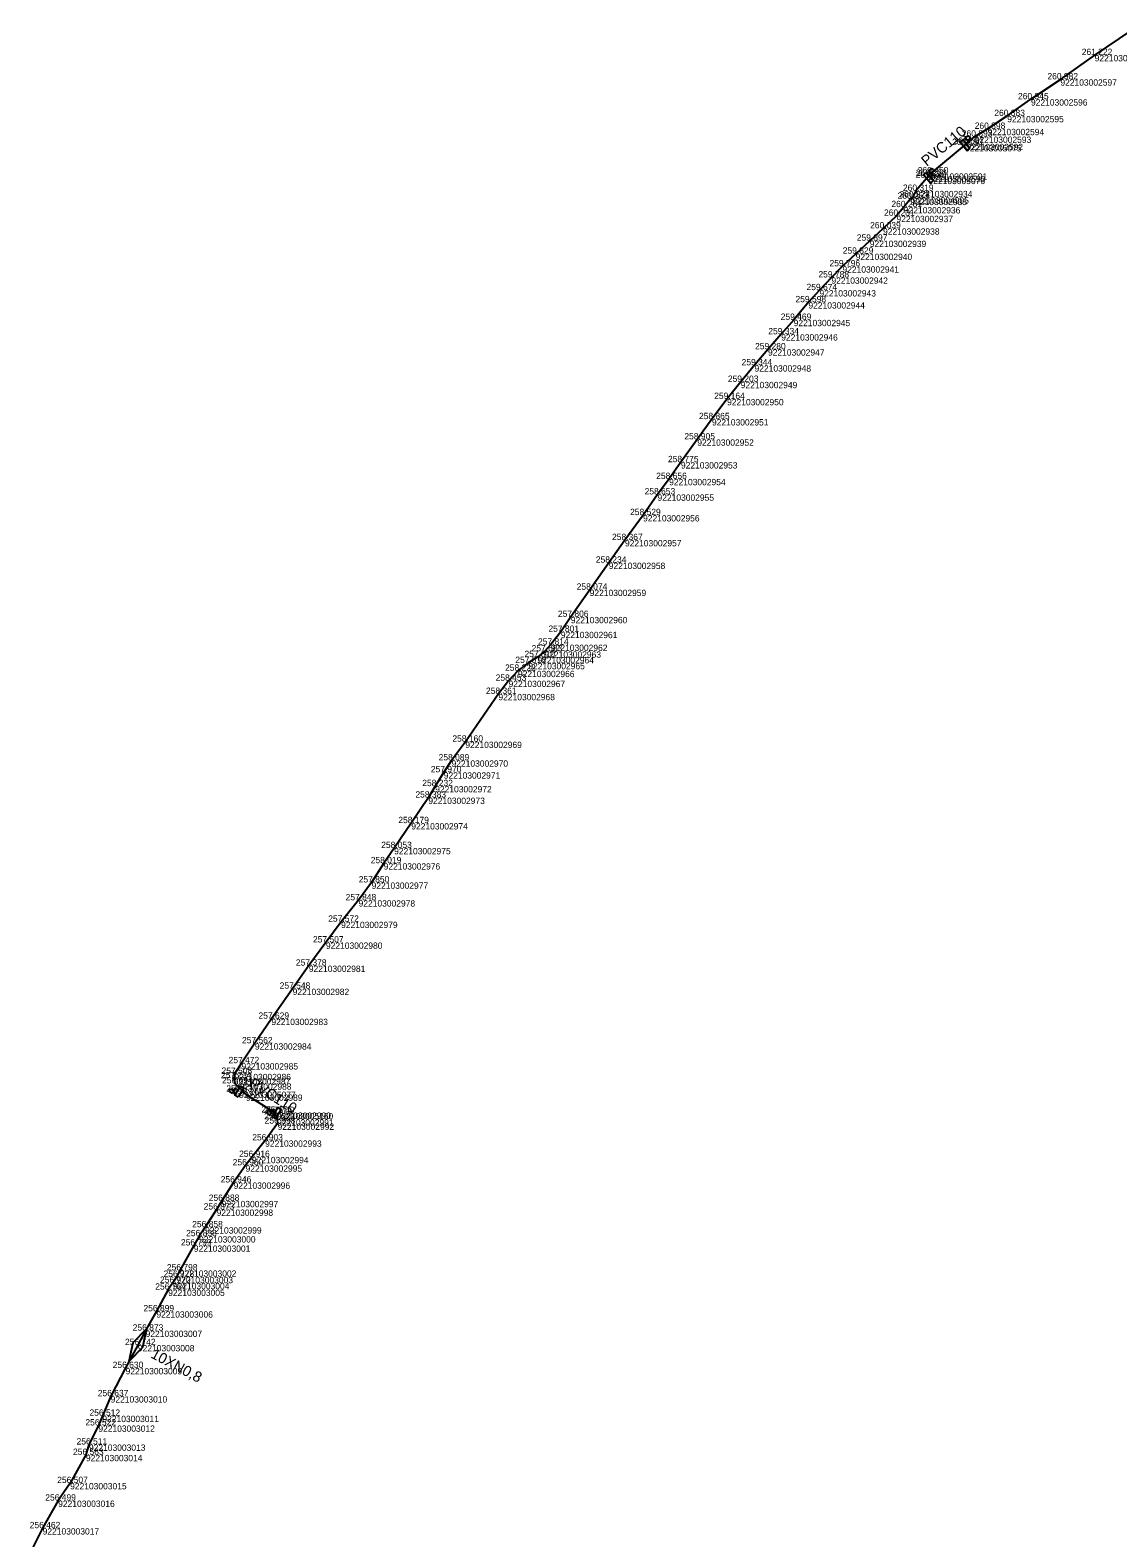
# Model space of a CAD drawing. Extents: x -771047 to -756200, y -1053876 to -1046520.
# Drawn here: x -762430.5 to -762224.4, y -1050712.5 to -1050426.6 of the extents above; entities that cross this region are included whole.
import ezdxf

# ---------------------------------------------------------------- set-up
doc = ezdxf.new("R2010")
doc.units = 0
for name, color, linetype in [('Vrstva 32', 7, 'Continuous'), ('Vrstva 33', 7, 'Continuous'), ('Vrstva 60', 7, 'Continuous'), ('Vrstva 61', 7, 'Continuous')]:
    doc.layers.add(name, color=color, linetype=linetype)

msp = doc.modelspace()

# ---------------------------------------------------------------- linework, layer by layer
at = {"layer": 'Vrstva 32'}
for points in [[(-762259.83, -1050453.72), (-762253.04, -1050448.11), (-762251.48, -1050446.73), (-762249.04, -1050445.27), (-762245.32, -1050442.83), (-762240.82, -1050439.66), (-762235.25, -1050435.88), (-762228.75, -1050431.27), (-762221.73, -1050426.55)], [(-762259.83, -1050453.72), (-762260.18, -1050454.18), (-762262.64, -1050457.03), (-762263.3, -1050458.27), (-762263.65, -1050458.53), (-762264.92, -1050460.11), (-762266.32, -1050461.76), (-762268.86, -1050464.14), (-762271.38, -1050466.48), (-762274.05, -1050468.94), (-762276.55, -1050471.34), (-762278.65, -1050473.45), (-762280.92, -1050475.86), (-762283.01, -1050478.15), (-762285.8, -1050481.49), (-762288.16, -1050484.22), (-762290.67, -1050487.07), (-762293.22, -1050490.1), (-762295.83, -1050493.25), (-762298.42, -1050496.49), (-762301.29, -1050500.32), (-762304.07, -1050504.16), (-762307.17, -1050508.48), (-762309.41, -1050511.66), (-762311.61, -1050514.6), (-762314.35, -1050518.52), (-762317.78, -1050523.25), (-762320.85, -1050527.54), (-762324.47, -1050532.67), (-762328.04, -1050537.82)], [(-762328.04, -1050537.82), (-762329.93, -1050540.65), (-762331.81, -1050543.08), (-762333.03, -1050544.35), (-762334.38, -1050545.44), (-762336.1, -1050546.55), (-762338.06, -1050548.04), (-762339.84, -1050549.93), (-762341.77, -1050552.42), (-762348.04, -1050561.48), (-762350.65, -1050565.03), (-762352.13, -1050567.29), (-762353.75, -1050569.91), (-762355.05, -1050572.08), (-762358.28, -1050576.93), (-762361.53, -1050581.65), (-762363.51, -1050584.53), (-762365.8, -1050588.18), (-762368.27, -1050591.55), (-762371.58, -1050595.63), (-762374.46, -1050599.56), (-762377.7, -1050603.94), (-762380.77, -1050608.32), (-762384.8, -1050614.02), (-762387.92, -1050618.68), (-762390.46, -1050622.45), (-762391.8, -1050624.47), (-762391.92, -1050625.3), (-762391.7, -1050626.29), (-762389.61, -1050628.39), (-762384.23, -1050631.8), (-762383.72, -1050633.11), (-762383.63, -1050633.9)], [(-762383.63, -1050633.9), (-762385.98, -1050637.1), (-762388.47, -1050640.22), (-762389.69, -1050641.83), (-762391.96, -1050645.07), (-762394.21, -1050648.56), (-762395.19, -1050650.2), (-762397.36, -1050653.56), (-762398.51, -1050655.26), (-762399.5, -1050657.02), (-762402.15, -1050661.75), (-762402.79, -1050662.97), (-762403.47, -1050664.11), (-762404.36, -1050665.38), (-762406.6, -1050669.5), (-762408.64, -1050673.17), (-762410.1, -1050675.89), (-762412.43, -1050680.25), (-762415.26, -1050685.6), (-762416.83, -1050689.31), (-762417.6, -1050691.15), (-762419.38, -1050694.76), (-762419.95, -1050696.73), (-762422.95, -1050702.07), (-762425.21, -1050705.39), (-762428.16, -1050710.63), (-762430.04, -1050714.29)], [(-762408.45, -1050672.8), (-762409.22, -1050676.36), (-762411.75, -1050678.97), (-762410.98, -1050675.42), (-762408.45, -1050672.8)]]:
    msp.add_lwpolyline(points, dxfattribs=at)
at = {"layer": 'Vrstva 33'}
for points in [[(-762254.25, -1050447.81), (-762253.67, -1050447.34), (-762252.39, -1050448.89), (-762252.97, -1050449.36)], [(-762261.17, -1050454.01), (-762260.59, -1050453.54), (-762259.31, -1050455.09), (-762259.89, -1050455.56)], [(-762391.13, -1050628.88), (-762391.75, -1050628.48), (-762390.67, -1050626.78), (-762390.05, -1050627.18)], [(-762384.02, -1050632.95), (-762384.65, -1050632.56), (-762383.57, -1050630.86), (-762382.94, -1050631.25)]]:
    msp.add_lwpolyline(points, close=True, dxfattribs=at)
for points in [[(-762253.28, -1050447), (-762252.87, -1050446.67)], [(-762252.48, -1050447.97), (-762253.28, -1050447)], [(-762252.48, -1050447.15), (-762252.88, -1050447.48)], [(-762252.87, -1050446.67), (-762252.72, -1050446.61), (-762252.5, -1050446.69), (-762252.43, -1050446.78), (-762252.39, -1050447.01), (-762252.48, -1050447.15)], [(-762259.83, -1050453.72), (-762253.04, -1050448.11)], [(-762260.2, -1050453.2), (-762259.79, -1050452.87)], [(-762259.4, -1050454.17), (-762260.2, -1050453.2)], [(-762259.4, -1050453.35), (-762259.8, -1050453.68)], [(-762259.79, -1050452.87), (-762259.64, -1050452.81), (-762259.42, -1050452.89), (-762259.35, -1050452.98), (-762259.31, -1050453.21), (-762259.4, -1050453.35)], [(-762392.64, -1050627.93), (-762392.74, -1050627.8), (-762392.73, -1050627.57), (-762392.67, -1050627.47), (-762392.46, -1050627.36), (-762392.31, -1050627.4)], [(-762392.31, -1050627.4), (-762391.87, -1050627.68)], [(-762391.53, -1050627.15), (-762392.2, -1050628.21)], [(-762392.2, -1050628.21), (-762392.64, -1050627.93)], [(-762389.61, -1050628.39), (-762384.23, -1050631.8)], [(-762385.53, -1050632), (-762385.64, -1050631.87), (-762385.62, -1050631.64), (-762385.56, -1050631.55), (-762385.36, -1050631.43), (-762385.2, -1050631.48)], [(-762385.09, -1050632.28), (-762385.53, -1050632)], [(-762385.2, -1050631.48), (-762384.76, -1050631.76)], [(-762384.42, -1050631.22), (-762385.09, -1050632.28)]]:
    msp.add_lwpolyline(points, dxfattribs=at)
at = {"layer": 'Vrstva 60'}
for p, q in [((-762228.75, -1050431.27), (-762228.75, -1050431.27)), ((-762235.25, -1050435.88), (-762235.25, -1050435.88)), ((-762240.82, -1050439.66), (-762240.82, -1050439.66)), ((-762245.32, -1050442.83), (-762245.32, -1050442.83)), ((-762251.48, -1050446.73), (-762251.48, -1050446.73)), ((-762249.04, -1050445.27), (-762249.04, -1050445.27)), ((-762253.32, -1050448.35), (-762253.32, -1050448.35)), ((-762253.04, -1050448.11), (-762253.04, -1050448.11)), ((-762260.24, -1050454.55), (-762260.24, -1050454.55)), ((-762260.18, -1050454.18), (-762260.18, -1050454.18)), ((-762259.83, -1050453.72), (-762259.83, -1050453.72)), ((-762263.65, -1050458.53), (-762263.65, -1050458.53)), ((-762263.3, -1050458.27), (-762263.3, -1050458.27)), ((-762262.64, -1050457.03), (-762262.64, -1050457.03)), ((-762266.32, -1050461.76), (-762266.32, -1050461.76)), ((-762264.92, -1050460.11), (-762264.92, -1050460.11)), ((-762268.86, -1050464.14), (-762268.86, -1050464.14)), ((-762271.38, -1050466.48), (-762271.38, -1050466.48)), ((-762274.05, -1050468.94), (-762274.05, -1050468.94)), ((-762276.55, -1050471.34), (-762276.55, -1050471.34)), ((-762280.92, -1050475.86), (-762280.92, -1050475.86)), ((-762278.65, -1050473.45), (-762278.65, -1050473.45)), ((-762283.01, -1050478.15), (-762283.01, -1050478.15)), ((-762285.8, -1050481.49), (-762285.8, -1050481.49)), ((-762288.16, -1050484.22), (-762288.16, -1050484.22)), ((-762290.67, -1050487.07), (-762290.67, -1050487.07)), ((-762293.22, -1050490.1), (-762293.22, -1050490.1)), ((-762295.83, -1050493.25), (-762295.83, -1050493.25)), ((-762298.42, -1050496.49), (-762298.42, -1050496.49)), ((-762301.29, -1050500.32), (-762301.29, -1050500.32)), ((-762304.07, -1050504.16), (-762304.07, -1050504.16)), ((-762307.17, -1050508.48), (-762307.17, -1050508.48)), ((-762309.41, -1050511.66), (-762309.41, -1050511.66)), ((-762311.61, -1050514.6), (-762311.61, -1050514.6)), ((-762314.35, -1050518.52), (-762314.35, -1050518.52)), ((-762317.78, -1050523.25), (-762317.78, -1050523.25)), ((-762320.85, -1050527.54), (-762320.85, -1050527.54)), ((-762324.47, -1050532.67), (-762324.47, -1050532.67)), ((-762328.04, -1050537.82), (-762328.04, -1050537.82)), ((-762329.93, -1050540.65), (-762329.93, -1050540.65)), ((-762333.03, -1050544.35), (-762333.03, -1050544.35)), ((-762331.81, -1050543.08), (-762331.81, -1050543.08)), ((-762336.1, -1050546.55), (-762336.1, -1050546.55)), ((-762334.38, -1050545.44), (-762334.38, -1050545.44)), ((-762339.84, -1050549.93), (-762339.84, -1050549.93)), ((-762338.06, -1050548.04), (-762338.06, -1050548.04)), ((-762341.77, -1050552.42), (-762341.77, -1050552.42)), ((-762348.04, -1050561.48), (-762348.04, -1050561.48)), ((-762352.13, -1050567.29), (-762352.13, -1050567.29)), ((-762350.65, -1050565.03), (-762350.65, -1050565.03)), ((-762353.75, -1050569.91), (-762353.75, -1050569.91)), ((-762355.05, -1050572.08), (-762355.05, -1050572.08)), ((-762358.28, -1050576.93), (-762358.28, -1050576.93)), ((-762361.53, -1050581.65), (-762361.53, -1050581.65)), ((-762363.51, -1050584.53), (-762363.51, -1050584.53)), ((-762365.8, -1050588.18), (-762365.8, -1050588.18)), ((-762368.27, -1050591.55), (-762368.27, -1050591.55)), ((-762371.58, -1050595.63), (-762371.58, -1050595.63)), ((-762374.46, -1050599.56), (-762374.46, -1050599.56)), ((-762377.7, -1050603.94), (-762377.7, -1050603.94)), ((-762380.77, -1050608.32), (-762380.77, -1050608.32)), ((-762384.8, -1050614.02), (-762384.8, -1050614.02)), ((-762387.92, -1050618.68), (-762387.92, -1050618.68)), ((-762391.8, -1050624.47), (-762391.8, -1050624.47)), ((-762390.46, -1050622.45), (-762390.46, -1050622.45)), ((-762391.92, -1050625.3), (-762391.92, -1050625.3)), ((-762391.7, -1050626.29), (-762391.7, -1050626.29)), ((-762390.9, -1050627.83), (-762390.9, -1050627.83)), ((-762389.61, -1050628.39), (-762389.61, -1050628.39)), ((-762384.23, -1050631.8), (-762384.23, -1050631.8)), ((-762383.79, -1050631.91), (-762383.79, -1050631.91)), ((-762383.72, -1050633.11), (-762383.72, -1050633.11)), ((-762383.63, -1050633.9), (-762383.63, -1050633.9)), ((-762385.98, -1050637.1), (-762385.98, -1050637.1)), ((-762389.69, -1050641.83), (-762389.69, -1050641.83)), ((-762388.47, -1050640.22), (-762388.47, -1050640.22)), ((-762391.96, -1050645.07), (-762391.96, -1050645.07)), ((-762395.19, -1050650.2), (-762395.19, -1050650.2)), ((-762394.21, -1050648.56), (-762394.21, -1050648.56)), ((-762397.36, -1050653.56), (-762397.36, -1050653.56)), ((-762398.51, -1050655.26), (-762398.51, -1050655.26)), ((-762399.5, -1050657.02), (-762399.5, -1050657.02)), ((-762402.15, -1050661.75), (-762402.15, -1050661.75)), ((-762403.47, -1050664.11), (-762403.47, -1050664.11)), ((-762402.79, -1050662.97), (-762402.79, -1050662.97)), ((-762404.36, -1050665.38), (-762404.36, -1050665.38)), ((-762406.6, -1050669.5), (-762406.6, -1050669.5)), ((-762408.64, -1050673.17), (-762408.64, -1050673.17)), ((-762410.1, -1050675.89), (-762410.1, -1050675.89)), ((-762412.43, -1050680.25), (-762412.43, -1050680.25)), ((-762415.26, -1050685.6), (-762415.26, -1050685.6)), ((-762416.83, -1050689.31), (-762416.83, -1050689.31)), ((-762417.6, -1050691.15), (-762417.6, -1050691.15)), ((-762419.38, -1050694.76), (-762419.38, -1050694.76)), ((-762419.95, -1050696.73), (-762419.95, -1050696.73)), ((-762422.95, -1050702.07), (-762422.95, -1050702.07)), ((-762425.21, -1050705.39), (-762425.21, -1050705.39)), ((-762428.16, -1050710.63), (-762428.16, -1050710.63))]:
    msp.add_line(p, q, dxfattribs=at)

# ---------------------------------------------------------------- texts
at = {"layer": 'Vrstva 32'}
msp.add_text('10XN0,8', height=2, rotation=331.8819, dxfattribs=at).set_placement((-762407.82, -1050678.2))
at = {"layer": 'Vrstva 33'}
for rotation, p in [(39.5773, (-762260.6, -1050452.46)), (327.6117, (-762389.19, -1050626.75))]:
    msp.add_text('PVC110', height=2, rotation=rotation, dxfattribs=at).set_placement(p)
at = {"layer": 'Vrstva 60'}
for s, p in [('922103002598', (-762228.75, -1050432.47)), ('922103002597', (-762235.25, -1050437.08)), ('922103002596', (-762240.82, -1050440.86)), ('922103002595', (-762245.32, -1050444.03)), ('922103002593', (-762251.48, -1050447.93)), ('922103002594', (-762249.04, -1050446.47)), ('922103005075', (-762253.32, -1050449.55)), ('922103002592', (-762253.04, -1050449.31)), ('922103005076', (-762260.24, -1050455.75)), ('922103002590', (-762260.18, -1050455.38)), ('922103002591', (-762259.83, -1050454.92)), ('922103002935', (-762263.65, -1050459.73)), ('922103004995', (-762263.3, -1050459.47)), ('922103002934', (-762262.64, -1050458.23)), ('922103002937', (-762266.32, -1050462.96)), ('922103002936', (-762264.92, -1050461.31)), ('922103002938', (-762268.86, -1050465.34)), ('922103002939', (-762271.38, -1050467.68)), ('922103002940', (-762274.05, -1050470.14)), ('922103002942', (-762278.65, -1050474.65)), ('922103002941', (-762276.55, -1050472.54)), ('922103002943', (-762280.92, -1050477.06)), ('922103002944', (-762283.01, -1050479.35)), ('922103002945', (-762285.8, -1050482.69)), ('922103002946', (-762288.16, -1050485.42)), ('922103002947', (-762290.67, -1050488.27)), ('922103002948', (-762293.22, -1050491.3)), ('922103002949', (-762295.83, -1050494.45)), ('922103002950', (-762298.42, -1050497.69)), ('922103002951', (-762301.29, -1050501.52)), ('922103002952', (-762304.07, -1050505.36)), ('922103002953', (-762307.17, -1050509.68)), ('922103002954', (-762309.41, -1050512.85)), ('922103002955', (-762311.61, -1050515.8)), ('922103002956', (-762314.35, -1050519.72)), ('922103002957', (-762317.78, -1050524.45)), ('922103002958', (-762320.85, -1050528.74)), ('922103002959', (-762324.47, -1050533.87)), ('922103002960', (-762328.04, -1050539.02)), ('922103002961', (-762329.93, -1050541.85)), ('922103002963', (-762333.03, -1050545.55)), ('922103002962', (-762331.81, -1050544.28)), ('922103002965', (-762336.1, -1050547.75)), ('922103002964', (-762334.38, -1050546.64)), ('922103002967', (-762339.84, -1050551.12)), ('922103002966', (-762338.06, -1050549.24)), ('922103002968', (-762341.77, -1050553.62)), ('922103002969', (-762348.04, -1050562.68)), ('922103002971', (-762352.13, -1050568.49)), ('922103002970', (-762350.65, -1050566.23)), ('922103002972', (-762353.75, -1050571.1)), ('922103002973', (-762355.05, -1050573.28)), ('922103002974', (-762358.28, -1050578.13)), ('922103002975', (-762361.53, -1050582.84)), ('922103002976', (-762363.51, -1050585.73)), ('922103002977', (-762365.8, -1050589.38)), ('922103002978', (-762368.27, -1050592.75)), ('922103002979', (-762371.58, -1050596.83)), ('922103002980', (-762374.46, -1050600.76)), ('922103002981', (-762377.7, -1050605.14)), ('922103002982', (-762380.77, -1050609.52)), ('922103002983', (-762384.8, -1050615.22)), ('922103002984', (-762387.92, -1050619.88)), ('922103002986', (-762391.8, -1050625.67)), ('922103002985', (-762390.46, -1050623.65)), ('922103002987', (-762391.92, -1050626.5)), ('922103002988', (-762391.7, -1050627.49)), ('922103005077', (-762390.9, -1050629.03)), ('922103002989', (-762389.61, -1050629.59)), ('922103002990', (-762384.23, -1050633)), ('922103005160', (-762383.79, -1050633.1)), ('922103002991', (-762383.72, -1050634.31)), ('922103002992', (-762383.63, -1050635.09)), ('922103002993', (-762385.98, -1050638.3)), ('922103002995', (-762389.69, -1050643.03)), ('922103002994', (-762388.47, -1050641.42)), ('922103002996', (-762391.96, -1050646.27)), ('922103002998', (-762395.19, -1050651.4)), ('922103002997', (-762394.21, -1050649.76)), ('922103002999', (-762397.36, -1050654.76)), ('922103003000', (-762398.51, -1050656.46)), ('922103003001', (-762399.5, -1050658.22)), ('922103003002', (-762402.15, -1050662.95)), ('922103003004', (-762403.47, -1050665.31)), ('922103003003', (-762402.79, -1050664.17)), ('922103003005', (-762404.36, -1050666.58)), ('922103003006', (-762406.6, -1050670.7)), ('922103003007', (-762408.64, -1050674.37)), ('922103003008', (-762410.1, -1050677.09)), ('922103003009', (-762412.43, -1050681.45)), ('922103003010', (-762415.26, -1050686.8)), ('922103003011', (-762416.83, -1050690.51)), ('922103003012', (-762417.6, -1050692.35)), ('922103003013', (-762419.38, -1050695.96)), ('922103003014', (-762419.95, -1050697.93)), ('922103003015', (-762422.95, -1050703.27)), ('922103003016', (-762425.21, -1050706.59)), ('922103003017', (-762428.16, -1050711.83))]:
    msp.add_text(s, height=1.2, dxfattribs=at).set_placement(p)
at = {"layer": 'Vrstva 61'}
for s, p in [('261.222', (-762231.2, -1050431.27)), ('260.982', (-762237.7, -1050435.88)), ('260.945', (-762243.28, -1050439.66)), ('260.883', (-762247.77, -1050442.83)), ('260.898', (-762251.49, -1050445.27)), ('262.150', (-762255.77, -1050448.35)), ('260.657', (-762255.49, -1050448.11)), ('260.893', (-762253.93, -1050446.73)), ('261.680', (-762262.69, -1050454.55)), ('260.227', (-762262.63, -1050454.18)), ('260.450', (-762262.28, -1050453.72)), ('260.319', (-762265.09, -1050457.03)), ('260.261', (-762267.28, -1050460.11)), ('260.253', (-762266.11, -1050458.53)), ('260.274', (-762265.75, -1050458.27)), ('260.231', (-762268.68, -1050461.76)), ('260.039', (-762271.31, -1050464.14)), ('259.829', (-762276.5, -1050468.94)), ('259.897', (-762273.84, -1050466.48)), ('259.796', (-762279.01, -1050471.34)), ('259.788', (-762281.11, -1050473.45)), ('259.674', (-762283.37, -1050475.86)), ('259.598', (-762285.46, -1050478.15)), ('259.469', (-762288.26, -1050481.49)), ('259.334', (-762290.61, -1050484.22)), ('259.280', (-762293.12, -1050487.07)), ('259.344', (-762295.67, -1050490.1)), ('259.203', (-762298.28, -1050493.25)), ('259.164', (-762300.87, -1050496.49)), ('258.865', (-762303.75, -1050500.32)), ('258.905', (-762306.52, -1050504.16)), ('258.775', (-762309.63, -1050508.48)), ('258.656', (-762311.86, -1050511.66)), ('258.653', (-762314.06, -1050514.6)), ('258.529', (-762316.81, -1050518.52)), ('258.367', (-762320.23, -1050523.25)), ('258.234', (-762323.3, -1050527.54)), ('258.074', (-762326.93, -1050532.67)), ('257.806', (-762330.49, -1050537.82)), ('257.814', (-762334.26, -1050543.08)), ('257.801', (-762332.29, -1050540.65)), ('257.810', (-762336.83, -1050545.44)), ('257.683', (-762335.48, -1050544.35)), ('258.222', (-762340.51, -1050548.04)), ('257.818', (-762338.56, -1050546.55)), ('258.453', (-762342.29, -1050549.93)), ('258.361', (-762344.13, -1050552.42)), ('258.160', (-762350.49, -1050561.48)), ('258.089', (-762353.1, -1050565.03)), ('257.970', (-762354.58, -1050567.29)), ('258.232', (-762356.2, -1050569.91)), ('258.383', (-762357.5, -1050572.08)), ('258.179', (-762360.74, -1050576.93)), ('258.053', (-762363.99, -1050581.65)), ('258.019', (-762365.97, -1050584.53)), ('257.850', (-762368.25, -1050588.18)), ('257.848', (-762370.73, -1050591.55)), ('257.572', (-762374.03, -1050595.63)), ('257.507', (-762376.92, -1050599.56)), ('257.378', (-762380.15, -1050603.94)), ('257.548', (-762383.23, -1050608.32)), ('257.629', (-762387.25, -1050614.02)), ('257.562', (-762390.37, -1050618.68)), ('257.472', (-762392.91, -1050622.45)), ('257.234', (-762394.37, -1050625.3)), ('257.508', (-762394.25, -1050624.47)), ('256.694', (-762394.15, -1050626.29)), ('257.630', (-762393.35, -1050627.83)), ('256.269', (-762392.06, -1050628.39)), ('256.176', (-762386.69, -1050631.8)), ('257.740', (-762386.24, -1050631.91)), ('256.623', (-762386.17, -1050633.11)), ('256.998', (-762386.08, -1050633.9)), ('256.903', (-762388.43, -1050637.1)), ('256.916', (-762390.92, -1050640.22)), ('256.960', (-762392.14, -1050641.83)), ('256.946', (-762394.41, -1050645.07)), ('256.888', (-762396.67, -1050648.56)), ('256.873', (-762397.64, -1050650.2)), ('256.858', (-762399.81, -1050653.56)), ('256.799', (-762401.95, -1050657.02)), ('256.838', (-762400.96, -1050655.26)), ('256.778', (-762405.24, -1050662.97)), ('256.798', (-762404.61, -1050661.75)), ('256.764', (-762406.81, -1050665.38)), ('256.770', (-762405.92, -1050664.11)), ('256.899', (-762409.05, -1050669.5)), ('256.873', (-762411.09, -1050673.17)), ('256.742', (-762412.55, -1050675.89)), ('256.630', (-762414.88, -1050680.25)), ('256.637', (-762417.71, -1050685.6)), ('256.522', (-762420.05, -1050691.15)), ('256.512', (-762419.28, -1050689.31)), ('256.511', (-762421.73, -1050694.76)), ('256.563', (-762422.4, -1050696.73)), ('256.507', (-762425.4, -1050702.07)), ('256.499', (-762427.66, -1050705.39)), ('256.462', (-762430.61, -1050710.63))]:
    msp.add_text(s, height=1.2, dxfattribs=at).set_placement(p)

doc.saveas('drawing.dxf')
